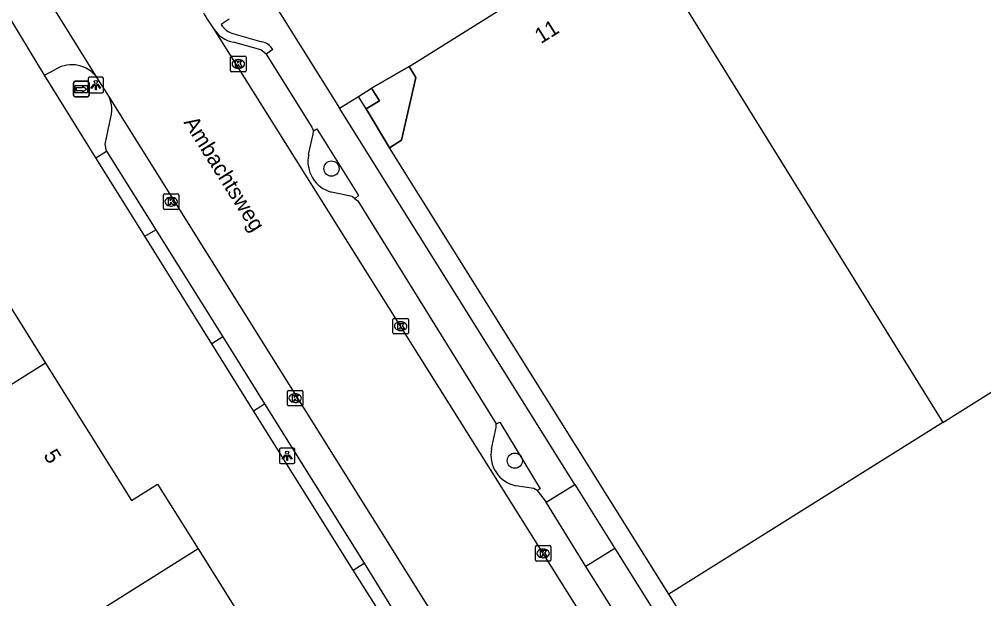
# Model space of a CAD drawing. Extents: x 158461 to 159795, y 387220 to 388672.
# Drawn here: x 158607.5 to 158669.4, y 387757.5 to 387794.7 of the extents above; entities that cross this region are included whole.
import ezdxf

# ---------------------------------------------------------------- set-up
doc = ezdxf.new("R2010")
doc.units = 0
for name, color, linetype in [('IMGEO_Boom', 7, 'Continuous'), ('IMGEO_Kolk', 7, 'Continuous'), ('IMGEO_Lichtpunt', 7, 'Continuous'), ('IMGEO_Openbare_ruimte_label', 7, 'Continuous'), ('IMGEO_Pand', 7, 'Continuous'), ('IMGEO_Pand_nummerreeks', 7, 'Continuous'), ('IMGEO_Pand_overbouw', 7, 'Continuous'), ('IMGEO_Parkeervlak_open', 7, 'Continuous'), ('IMGEO_Rijbaan_lokaal_gesloten', 7, 'Continuous'), ('IMGEO_Rijbaan_lokaal_open', 7, 'Continuous'), ('IMGEO_Voetpad_open', 7, 'Continuous'), ('IMGEO_Wegwijzer', 7, 'Continuous')]:
    doc.layers.add(name, color=color, linetype=linetype)

msp = doc.modelspace()

# ---------------------------------------------------------------- linework, layer by layer
at = {"layer": 'IMGEO_Boom'}
for centre in [(158627.525, 387785.138), (158639.297, 387766.394)]:
    msp.add_circle(centre, 0.489, dxfattribs=at)
at = {"layer": 'IMGEO_Kolk'}
for p, q in [((158621.043, 387791.429), (158621.043, 387792.281)), ((158621.118, 387792.355), (158621.97, 387792.355)), ((158621.531, 387792.135), (158621.556, 387792.135)), ((158622.044, 387792.281), (158622.044, 387791.429)), ((158621.97, 387791.355), (158621.118, 387791.355)), ((158621.554, 387791.575), (158621.529, 387791.575)), ((158616.731, 387782.589), (158616.731, 387783.441)), ((158616.806, 387783.515), (158617.658, 387783.515)), ((158617.219, 387783.295), (158617.244, 387783.295)), ((158617.732, 387783.441), (158617.732, 387782.589)), ((158617.242, 387782.735), (158617.217, 387782.735)), ((158617.658, 387782.515), (158616.806, 387782.515)), ((158631.469, 387774.601), (158631.469, 387775.453)), ((158631.544, 387775.527), (158632.396, 387775.527)), ((158631.957, 387775.307), (158631.982, 387775.307)), ((158632.47, 387775.453), (158632.47, 387774.601)), ((158631.98, 387774.747), (158631.955, 387774.747)), ((158632.396, 387774.527), (158631.544, 387774.527)), ((158624.768, 387770.908), (158625.62, 387770.908)), ((158624.693, 387769.982), (158624.693, 387770.834)), ((158625.181, 387770.688), (158625.206, 387770.688)), ((158625.694, 387770.834), (158625.694, 387769.982)), ((158625.62, 387769.908), (158624.768, 387769.908)), ((158625.204, 387770.128), (158625.179, 387770.128)), ((158640.618, 387760.015), (158640.618, 387760.867)), ((158640.693, 387760.941), (158641.545, 387760.941)), ((158641.106, 387760.721), (158641.131, 387760.721)), ((158641.619, 387760.867), (158641.619, 387760.015)), ((158641.545, 387759.941), (158640.693, 387759.941)), ((158641.129, 387760.161), (158641.104, 387760.161))]:
    msp.add_line(p, q, dxfattribs=at)
for points in [[(158621.043, 387791.429), (158621.043, 387792.281)], [(158621.118, 387792.355), (158621.97, 387792.355)], [(158621.364, 387792.055), (158621.487, 387792.055), (158621.487, 387791.904), (158621.617, 387792.055), (158621.781, 387792.055), (158621.635, 387791.904), (158621.788, 387791.655), (158621.636, 387791.655), (158621.551, 387791.819), (158621.487, 387791.752), (158621.487, 387791.655), (158621.364, 387791.655), (158621.364, 387792.055)], [(158622.044, 387792.281), (158622.044, 387791.429)], [(158621.97, 387791.355), (158621.118, 387791.355)], [(158616.731, 387782.589), (158616.731, 387783.441)], [(158616.806, 387783.515), (158617.658, 387783.515)], [(158617.732, 387783.441), (158617.732, 387782.589)], [(158617.052, 387783.215), (158617.175, 387783.215), (158617.175, 387783.064), (158617.305, 387783.215), (158617.469, 387783.215), (158617.323, 387783.064), (158617.476, 387782.815), (158617.324, 387782.815), (158617.239, 387782.979), (158617.175, 387782.912), (158617.175, 387782.815), (158617.052, 387782.815), (158617.052, 387783.215)], [(158617.658, 387782.515), (158616.806, 387782.515)], [(158631.469, 387774.601), (158631.469, 387775.453)], [(158631.544, 387775.527), (158632.396, 387775.527)], [(158631.79, 387775.227), (158631.913, 387775.227), (158631.913, 387775.076), (158632.043, 387775.227), (158632.207, 387775.227), (158632.061, 387775.076), (158632.214, 387774.827), (158632.062, 387774.827), (158631.977, 387774.991), (158631.913, 387774.924), (158631.913, 387774.827), (158631.79, 387774.827), (158631.79, 387775.227)], [(158632.47, 387775.453), (158632.47, 387774.601)], [(158632.396, 387774.527), (158631.544, 387774.527)], [(158624.768, 387770.908), (158625.62, 387770.908)], [(158624.693, 387769.982), (158624.693, 387770.834)], [(158625.014, 387770.608), (158625.137, 387770.608), (158625.137, 387770.457), (158625.267, 387770.608), (158625.431, 387770.608), (158625.285, 387770.457), (158625.438, 387770.208), (158625.286, 387770.208), (158625.201, 387770.372), (158625.137, 387770.305), (158625.137, 387770.208), (158625.014, 387770.208), (158625.014, 387770.608)], [(158625.694, 387770.834), (158625.694, 387769.982)], [(158625.62, 387769.908), (158624.768, 387769.908)], [(158640.618, 387760.015), (158640.618, 387760.867)], [(158640.693, 387760.941), (158641.545, 387760.941)], [(158640.939, 387760.641), (158641.062, 387760.641), (158641.062, 387760.49), (158641.192, 387760.641), (158641.356, 387760.641), (158641.21, 387760.49), (158641.363, 387760.241), (158641.211, 387760.241), (158641.126, 387760.405), (158641.062, 387760.338), (158641.062, 387760.241), (158640.939, 387760.241), (158640.939, 387760.641)], [(158641.619, 387760.867), (158641.619, 387760.015)], [(158641.545, 387759.941), (158640.693, 387759.941)]]:
    msp.add_lwpolyline(points, dxfattribs=at)
for centre, start, end in [((158621.12, 387792.279), 91.55205, 178.44795), ((158621.12, 387792.279), 91.55205, 178.44795), ((158621.968, 387792.279), 1.55205, 88.44795), ((158621.968, 387792.279), 1.55205, 88.44795), ((158621.12, 387791.431), 181.55205, 268.44795), ((158621.12, 387791.431), 181.55205, 268.44795), ((158621.968, 387791.431), 271.55205, 358.44795), ((158621.968, 387791.431), 271.55205, 358.44795), ((158616.808, 387783.439), 91.55205, 178.44795), ((158616.808, 387783.439), 91.55205, 178.44795), ((158617.656, 387783.439), 1.55205, 88.44795), ((158617.656, 387783.439), 1.55205, 88.44795), ((158616.808, 387782.591), 181.55205, 268.44795), ((158616.808, 387782.591), 181.55205, 268.44795), ((158617.656, 387782.591), 271.55205, 358.44795), ((158617.656, 387782.591), 271.55205, 358.44795), ((158631.546, 387775.451), 91.55205, 178.44795), ((158631.546, 387775.451), 91.55205, 178.44795), ((158632.394, 387775.451), 1.55205, 88.44795), ((158632.394, 387775.451), 1.55205, 88.44795), ((158631.546, 387774.603), 181.55205, 268.44795), ((158631.546, 387774.603), 181.55205, 268.44795), ((158632.394, 387774.603), 271.55205, 358.44795), ((158632.394, 387774.603), 271.55205, 358.44795), ((158624.77, 387770.832), 91.55205, 178.44795), ((158624.77, 387770.832), 91.55205, 178.44795), ((158625.618, 387770.832), 1.55205, 88.44795), ((158625.618, 387770.832), 1.55205, 88.44795), ((158624.77, 387769.984), 181.55205, 268.44795), ((158624.77, 387769.984), 181.55205, 268.44795), ((158625.618, 387769.984), 271.55205, 358.44795), ((158625.618, 387769.984), 271.55205, 358.44795), ((158640.695, 387760.865), 91.55205, 178.44795), ((158640.695, 387760.865), 91.55205, 178.44795), ((158641.543, 387760.865), 1.55205, 88.44795), ((158641.543, 387760.865), 1.55205, 88.44795), ((158640.695, 387760.017), 181.55205, 268.44795), ((158640.695, 387760.017), 181.55205, 268.44795), ((158641.543, 387760.017), 271.55205, 358.44795), ((158641.543, 387760.017), 271.55205, 358.44795)]:
    msp.add_arc(centre, 0.0765, start, end, dxfattribs=at)
for centre, major_axis, ratio, start_param, end_param in [((158621.53, 387791.855), (-0.387, 0.002), 0.722429, 4.712389, 7.853982), ((158621.555, 387791.855), (-0.39, 0.002), 0.717154, 1.570796, 4.712389), ((158617.218, 387783.015), (-0.387, 0.002), 0.722429, 4.712389, 7.853982), ((158617.243, 387783.015), (-0.39, 0.002), 0.717154, 1.570796, 4.712389), ((158631.956, 387775.027), (-0.387, 0.002), 0.722429, 4.712389, 7.853982), ((158631.981, 387775.027), (-0.39, 0.002), 0.717154, 1.570796, 4.712389), ((158625.18, 387770.408), (-0.387, 0.002), 0.722429, 4.712389, 7.853982), ((158625.205, 387770.408), (-0.39, 0.002), 0.717154, 1.570796, 4.712389), ((158641.105, 387760.441), (-0.387, 0.002), 0.722429, 4.712389, 7.853982), ((158641.13, 387760.441), (-0.39, 0.002), 0.717154, 1.570796, 4.712389)]:
    msp.add_ellipse(centre, major_axis=major_axis, ratio=ratio, start_param=start_param, end_param=end_param, dxfattribs=at)
at = {"layer": 'IMGEO_Lichtpunt'}
for p, q in [((158611.894, 387790.902), (158611.894, 387790.095)), ((158611.894, 387790.902), (158611.894, 387790.095)), ((158612.796, 387790.997), (158611.988, 387790.997)), ((158612.796, 387790.997), (158611.988, 387790.997)), ((158612.89, 387790.095), (158612.89, 387790.902)), ((158612.89, 387790.095), (158612.89, 387790.902)), ((158611.988, 387790.001), (158612.796, 387790.001)), ((158611.988, 387790.001), (158612.796, 387790.001)), ((158625.085, 387767.207), (158624.277, 387767.207)), ((158625.085, 387767.207), (158624.277, 387767.207)), ((158624.183, 387767.112), (158624.183, 387766.305)), ((158624.183, 387767.112), (158624.183, 387766.305)), ((158625.179, 387766.305), (158625.179, 387767.112)), ((158625.179, 387766.305), (158625.179, 387767.112)), ((158624.277, 387766.211), (158625.085, 387766.211)), ((158624.277, 387766.211), (158625.085, 387766.211))]:
    msp.add_line(p, q, dxfattribs=at)
for points in [[(158612.268, 387790.566), (158612.307, 387790.538), (158612.119, 387790.276), (158612.081, 387790.303), (158612.268, 387790.566)], [(158612.37, 387790.518), (158612.417, 387790.518), (158612.417, 387790.196), (158612.37, 387790.196), (158612.37, 387790.518)], [(158612.48, 387790.538), (158612.518, 387790.565), (158612.705, 387790.303), (158612.666, 387790.275), (158612.48, 387790.538)], [(158624.557, 387766.776), (158624.596, 387766.748), (158624.408, 387766.486), (158624.37, 387766.513), (158624.557, 387766.776)], [(158624.659, 387766.728), (158624.706, 387766.728), (158624.706, 387766.406), (158624.659, 387766.406), (158624.659, 387766.728)], [(158624.769, 387766.748), (158624.807, 387766.775), (158624.994, 387766.513), (158624.955, 387766.485), (158624.769, 387766.748)]]:
    msp.add_lwpolyline(points, dxfattribs=at)
for centre in [(158612.393, 387790.7), (158624.682, 387766.91)]:
    msp.add_circle(centre, 0.0994, dxfattribs=at)
for centre, start, end in [((158611.988, 387790.902), 90, 180), ((158611.988, 387790.902), 90, 180), ((158612.796, 387790.902), 0, 90), ((158612.796, 387790.902), 0, 90), ((158611.988, 387790.095), 180, 270), ((158611.988, 387790.095), 180, 270), ((158612.796, 387790.095), 270, 0), ((158612.796, 387790.095), 270, 360), ((158624.277, 387767.112), 90, 180), ((158624.277, 387767.112), 90, 180), ((158625.085, 387767.112), 0, 90), ((158625.085, 387767.112), 0, 90), ((158624.277, 387766.305), 180, 270), ((158624.277, 387766.305), 180, 270), ((158625.085, 387766.305), 270, 0), ((158625.085, 387766.305), 270, 360)]:
    msp.add_arc(centre, 0.0946, start, end, dxfattribs=at)
at = {"layer": 'IMGEO_Pand'}
for points in [[(158632.509, 387791.689), (158647.008, 387800.772)], [(158647.008, 387800.772), (158666.776, 387768.852)], [(158632.509, 387791.689), (158632.948, 387790.988), (158632.023, 387786.961), (158631.246, 387786.474)], [(158629.257, 387789.774), (158630.097, 387790.3)], [(158629.763, 387788.967), (158630.603, 387789.493), (158630.097, 387790.3)], [(158629.763, 387788.967), (158629.257, 387789.774)], [(158585.81, 387757.993), (158577.633, 387771.021), (158602.63, 387786.71), (158605.28, 387782.489), (158603.633, 387781.456), (158609.16, 387772.65)], [(158649.189, 387757.833), (158631.246, 387786.474)], [(158666.776, 387768.852), (158666.941, 387768.955), (158684.676, 387780.065)], [(158609.16, 387772.65), (158585.81, 387757.993)], [(158609.16, 387772.65), (158614.686, 387763.844), (158616.352, 387764.89), (158618.961, 387760.732)], [(158666.776, 387768.852), (158649.189, 387757.833)], [(158618.961, 387760.732), (158601.864, 387750), (158593.946, 387745.03)], [(158618.961, 387760.732), (158621.571, 387756.574), (158619.943, 387755.552), (158623.428, 387750), (158625.43, 387746.81)], [(158658.943, 387742.264), (158654.096, 387750), (158649.189, 387757.833)]]:
    msp.add_lwpolyline(points, dxfattribs=at)
at = {"layer": 'IMGEO_Pand_overbouw'}
msp.add_lwpolyline([(158630.097, 387790.3), (158630.603, 387789.493), (158629.763, 387788.967), (158631.246, 387786.474), (158632.023, 387786.961), (158632.948, 387790.988), (158632.509, 387791.689)], close=True, dxfattribs=at)
at = {"layer": 'IMGEO_Parkeervlak_open'}
msp.add_lwpolyline([(158628.044, 387789.015), (158629.257, 387789.774)], dxfattribs=at)
at = {"layer": 'IMGEO_Rijbaan_lokaal_gesloten'}
for points in [[(158612.487, 387790.962), (158604.563, 387803.663)], [(158619.975, 387794.084), (158658.086, 387733.37)], [(158613.13, 387789.962), (158612.487, 387790.962)], [(158651.556, 387728.566), (158613.13, 387789.962)], [(158613.071, 387786.258), (158612.996, 387786.708), (158613.353, 387788.446)], [(158613.071, 387786.258), (158616.245, 387781.213)], [(158616.245, 387781.213), (158620.548, 387774.346)], [(158620.548, 387774.346), (158623.218, 387770.038)], [(158623.218, 387770.038), (158629.618, 387759.81)], [(158629.618, 387759.81), (158632.513, 387755.122)]]:
    msp.add_lwpolyline(points, dxfattribs=at)
for centre, radius, start, end in [((158627.858, 387799.784), 9.728, 208.47274, 215.8672), ((158611.46, 387788.942), 1.957, 345.32124, 31.41488)]:
    msp.add_arc(centre, radius, start, end, dxfattribs=at)
at = {"layer": 'IMGEO_Rijbaan_lokaal_open'}
for points in [[(158609.105, 387791.13), (158606.512, 387795.408)], [(158612.393, 387785.832), (158609.105, 387791.13)], [(158615.536, 387780.798), (158612.393, 387785.832)], [(158619.852, 387773.902), (158615.536, 387780.798)], [(158622.527, 387769.593), (158619.852, 387773.902)], [(158628.919, 387759.376), (158622.527, 387769.593)], [(158631.839, 387754.762), (158628.919, 387759.376)]]:
    msp.add_lwpolyline(points, dxfattribs=at)
at = {"layer": 'IMGEO_Voetpad_open'}
for points in [[(158621.719, 387799.125), (158628.044, 387789.015)], [(158620.959, 387794.721), (158620.445, 387794.396)], [(158621.256, 387793.793), (158623.064, 387793.278)], [(158623.336, 387792.474), (158622.984, 387792.753), (158621.227, 387793.262)], [(158623.754, 387792.777), (158623.336, 387792.474)], [(158623.336, 387792.474), (158626.257, 387787.808), (158626.369, 387787.557)], [(158609.105, 387791.13), (158609.826, 387791.526)], [(158630.097, 387790.3), (158632.509, 387791.689)], [(158643.152, 387764.867), (158628.044, 387789.015)], [(158631.246, 387786.474), (158629.763, 387788.967)], [(158626.369, 387787.557), (158626.579, 387787.683), (158629.261, 387783.412), (158629.034, 387783.208)], [(158626.061, 387786.044), (158626.353, 387787.341), (158626.369, 387787.557)], [(158612.393, 387785.832), (158613.071, 387786.258)], [(158629.034, 387783.208), (158628.855, 387783.34), (158627.529, 387783.626)], [(158629.034, 387783.208), (158629.226, 387783.068), (158638.105, 387768.751)], [(158615.536, 387780.798), (158616.245, 387781.213)], [(158620.548, 387774.346), (158619.852, 387773.902)], [(158622.527, 387769.593), (158623.218, 387770.038)], [(158637.808, 387767.147), (158638.1, 387768.531), (158638.105, 387768.751)], [(158638.105, 387768.751), (158638.328, 387768.857), (158640.924, 387764.592), (158640.729, 387764.482)], [(158640.729, 387764.482), (158640.525, 387764.617), (158639.358, 387764.787)], [(158641.319, 387763.74), (158643.152, 387764.867)], [(158643.152, 387764.867), (158645.719, 387760.76)], [(158640.729, 387764.482), (158641.319, 387763.74)], [(158643.855, 387759.6), (158641.319, 387763.74)], [(158645.719, 387760.76), (158643.855, 387759.6)], [(158645.719, 387760.76), (158663.134, 387732.954)], [(158628.919, 387759.376), (158629.618, 387759.81)], [(158649.318, 387750.757), (158649.245, 387751.048), (158643.855, 387759.6)]]:
    msp.add_lwpolyline(points, dxfattribs=at)
for centre, radius, start, end in [((158621.56, 387795.049), 1.292, 210.34753, 256.38891), ((158621.555, 387795.126), 1.892, 213.40061, 260.02563), ((158622.856, 387792.265), 1.034, 29.66027, 78.3739), ((158610.847, 387789.783), 2.02, 35.70788, 120.35859), ((158628.059, 387785.602), 2.046, 167.52541, 254.99958), ((158639.762, 387766.742), 1.996, 168.28348, 258.30871)]:
    msp.add_arc(centre, radius, start, end, dxfattribs=at)
at = {"layer": 'IMGEO_Wegwijzer'}
for p, q in [((158611.067, 387790.741), (158611.857, 387790.741)), ((158611.857, 387790.741), (158611.067, 387790.741)), ((158610.967, 387789.841), (158610.967, 387790.641)), ((158610.967, 387790.641), (158610.967, 387789.841)), ((158611.957, 387790.641), (158611.957, 387789.841)), ((158611.957, 387789.841), (158611.957, 387790.641)), ((158611.857, 387789.741), (158611.067, 387789.741)), ((158611.067, 387789.741), (158611.857, 387789.741))]:
    msp.add_line(p, q, dxfattribs=at)
for points in [[(158611.068, 387790.473), (158611.856, 387790.473), (158611.856, 387790.009), (158611.068, 387790.009), (158611.068, 387790.473)], [(158611.133, 387790.325), (158611.133, 387790.241), (158611.133, 387790.157), (158611.544, 387790.157), (158611.544, 387790.074), (158611.791, 387790.241), (158611.544, 387790.408), (158611.544, 387790.325), (158611.133, 387790.325)]]:
    msp.add_lwpolyline(points, dxfattribs=at)
for centre, start, end in [((158611.067, 387790.641), 90, 180), ((158611.067, 387790.641), 90, 180), ((158611.857, 387790.641), 0, 90), ((158611.857, 387790.641), 360, 90), ((158611.067, 387789.841), 180, 270), ((158611.067, 387789.841), 180, 270), ((158611.857, 387789.841), 270, 0), ((158611.857, 387789.841), 270, 0)]:
    msp.add_arc(centre, 0.1, start, end, dxfattribs=at)

# ---------------------------------------------------------------- texts
at = {"layer": 'IMGEO_Openbare_ruimte_label'}
msp.add_text('Ambachtsweg', height=1, rotation=302.08436, dxfattribs=at).set_placement((158618.005, 387788.11))
at = {"layer": 'IMGEO_Pand_nummerreeks'}
for s, rotation, p in [('11', 32.06573, (158640.973, 387793.122)), ('5', 302.1117, (158608.998, 387766.736))]:
    msp.add_text(s, height=1, rotation=rotation, dxfattribs=at).set_placement(p)

doc.saveas('drawing.dxf')
